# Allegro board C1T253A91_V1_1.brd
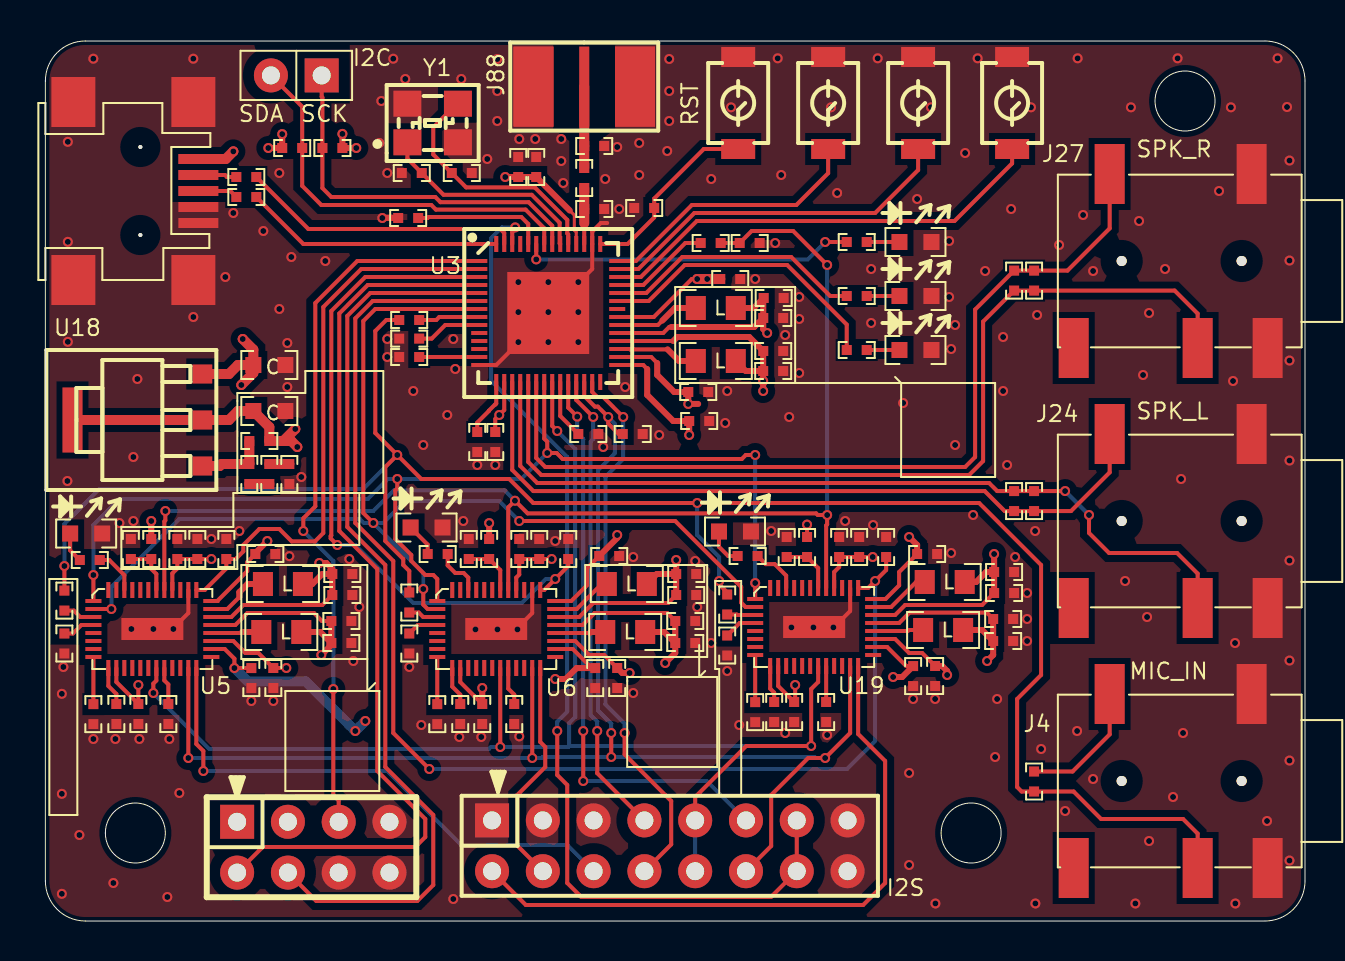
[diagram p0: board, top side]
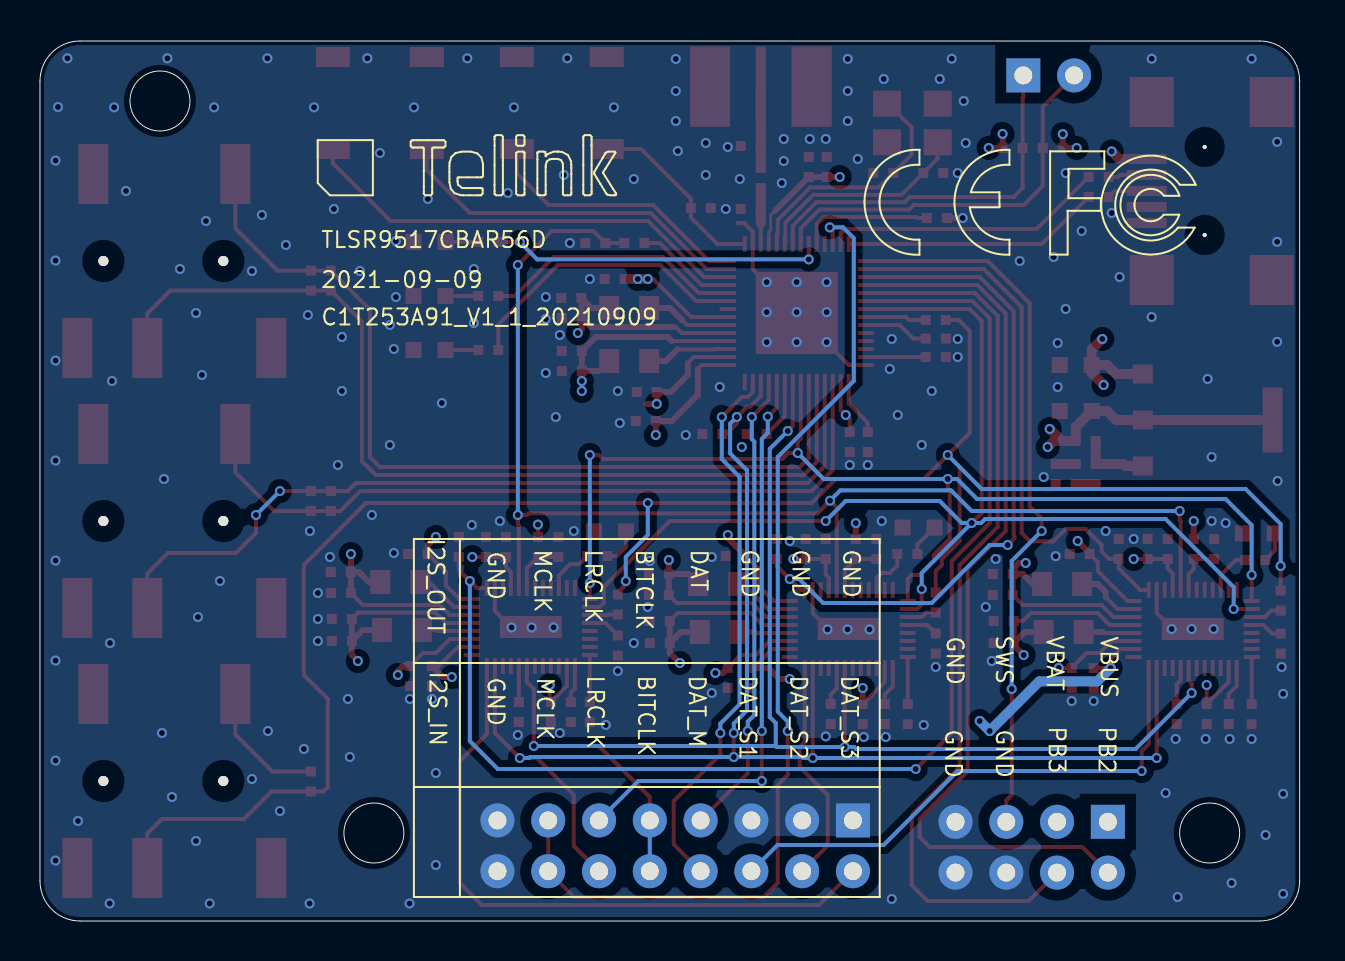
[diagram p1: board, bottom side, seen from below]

Outline 63 x 44 mm; copper layers: TOP, GND, POWER, BOTTOM. Coordinates in mm from the lower left corner of the outline.
Outline path: circle c4.5,4.4 r1.5 ; circle c46.3,4.4 r1.5 ; circle c57,41 r1.5 ; 0,42 0,2 arc(0.59,0.59) 2,0 61,0 arc(62.41,0.59) 63,2 63,42 arc(62.41,43.41) 61,44 2,44 arc(0.59,43.41) 0,42

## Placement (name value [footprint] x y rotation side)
C5  1.8pF  [0402]  27.45 35.6 180 top
C6  1pF  [0402]  27.45 38.75 180 top
C9  0.1uF  [0402]  23.65 37.7 90 top
C10  2.2uF  [0402]  24.55 37.7 90 top
C11  1uF  [0402]  29.95 35.65 180 top
C12  NC  [0402]  20.82 37.4 180 top
C13  NC  [0402]  18.32 37.4 0 top
C14  1uF  [0402]  34.25 32.1 0 top
C15  1uF  [0402]  36.42 31.15 0 top
C16  1uF  [0402]  36.4 30.15 0 top
C18  1uF  [0402]  18.2 28.2 180 top
C19  1uF  [0402]  32.65 26.45 0 top
C20  1uF  [0402]  36.4 28.5 0 top
C21  1uF  [0402]  32.7 25 0 top
C22  1uF  [0402]  36.4 27.5 0 top
C23  1uF  [0402]  21.6 23.95 270 top
C24  1uF  [0402]  22.5 23.95 270 top
C25  33pF  [0402]  29.38 24.35 0 top
C26  1uF  [0402]  27.15 24.35 0 top
C29  0.1uF  [0402]  7.6 18.6 90 top
C30  2.2uF  [0402]  6.6 18.6 90 top
C31  1uF  [0402]  9.05 18.6 90 top
C32  1uF  [0402]  11 18.35 0 top
C33  1uF  [0402]  14.85 17.35 0 top
C34  1uF  [0402]  14.85 16.3 0 top
C36  1uF  [0402]  11.4 12.15 270 top
C37  1uF  [0402]  14.8 15 0 top
C38  1uF  [0402]  2.4 10.34 270 top
C39  1uF  [0402]  10.3 12.15 270 top
C40  1uF  [0402]  14.8 13.9 0 top
C41  1uF  [0402]  3.55 10.35 270 top
C42  1uF  [0402]  4.65 10.35 270 top
C43  1uF  [0402]  6.15 10.35 270 top
C44  0.1uF  [0402]  24.7 18.6 90 top
C45  2.2uF  [0402]  23.7 18.6 90 top
C46  1uF  [0402]  26.15 18.6 90 top
C47  1uF  [0402]  28.6 12.15 270 top
C48  1uF  [0402]  21.85 10.35 270 top
C49  1uF  [0402]  32.05 16.3 0 top
C51  1uF  [0402]  28.2 18.25 0 top
C52  1uF  [0402]  32 13.9 0 top
C53  1uF  [0402]  19.6 10.34 270 top
C54  1uF  [0402]  27.5 12.15 270 top
C55  1uF  [0402]  32 15 0 top
C56  1uF  [0402]  20.75 10.35 270 top
C57  1uF  [0402]  32.05 17.35 0 top
C58  1uF  [0402]  23.45 10.35 270 top
C59  1uF  [0402]  18.2 30.05 0 top
C60  1uF  [0402]  18.2 29.12 0 top
C121  10uF  [0603C]  11.2 27.8 0 top
C122  10uF  [0603C]  11.2 25.5 0 top
C123  1uF  [0402]  35.5 10.44 270 top
C124  1uF  [0402]  37.45 10.45 270 top
C125  1uF  [0402]  36.45 10.45 270 top
C126  1uF  [0402]  39.05 10.45 270 top
C127  1uF  [0402]  47.9 15.1 0 top
C128  1uF  [0402]  44.1 18.35 0 top
C129  1uF  [0402]  47.95 17.45 0 top
C130  1uF  [0402]  43.4 12.25 270 top
C131  1uF  [0402]  44.5 12.25 270 top
C132  1uF  [0402]  47.95 16.4 0 top
C133  1uF  [0402]  47.9 14 0 top
C134  1uF  [0402]  42.05 18.7 90 top
C135  0.1uF  [0402]  40.7 18.7 90 top
C136  2.2uF  [0402]  39.7 18.7 90 top
C138  NC  [0402]  48.45 21 90 top
C140  1uF  [0402]  0.95 16.02 270 top
C141  1uF  [0402]  0.95 13.88 90 top
C142  1uF  [0402]  18.2 13.88 90 top
C143  1uF  [0402]  18.2 15.93 270 top
C144  1uF  [0402]  34.1 13.78 90 top
C145  1uF  [0402]  34.1 15.82 270 top
C146  NC  [0402]  48.45 32.02 270 top
D1  Blue  [0603-LED]  43.52 31.25 0 top
D2  Red  [0603-LED]  43.52 28.55 0 top
D4  Green  [0603-LED]  2.04 19.38 0 top
D5  Green  [0603-LED]  19.06 19.68 0 top
D6  Green  [0603-LED]  34.49 19.48 0 top
D7  Green  [0603-LED]  43.52 33.95 0 top
J3  I2C  [HDR254F-1X2X850]  11.28 42.28 0 top
J4  AIL1  [PJ-327]  62.83 7 270 top
J16  AUDIO_IN  [HDR254F-2X8X850]  40.12 5.03 180 top
J24  AOPHR  [PJ-327]  62.83 20 270 top
J27  AOPHR  [PJ-327]  62.83 33 270 top
J30  USB_MiniABF  [USB-MINI-F5]  7.65 36.5 270 top
J88  RFIN  [SMA-H]  26.95 41.72 90 top
J97  DEBUG  [HDR254F-2X4X850]  19.75 4.96 180 top
L3  2.4nH  [0402]  26.95 37.15 90 top
L4  10uH  [0805L]  33.53 30.65 0 top
L5  10uH  [0805L]  33.53 28 0 top
L6  10uH  [0805L]  11.88 16.85 0 top
L7  10uH  [0805L]  11.8 14.45 0 top
L8  10uH  [0805L]  29.08 16.85 0 top
L9  10uH  [0805L]  29 14.45 0 top
L10  10uH  [0805L]  44.9 14.55 0 top
L11  10uH  [0805L]  44.98 16.95 0 top
R1  4.7K  [0402]  18.14 35.15 0 top
R2  1K  [0402]  40.58 31.25 0 top
R3  1K  [0402]  40.58 28.55 0 top
R6  NC  [0402]  49.45 21 90 top
R13  2.2K  [0402]  12.35 38.65 0 top
R14  2.2K  [0402]  14.36 38.65 180 top
R23  510R  [0402]  33.27 33.9 0 top
R26  240R  [0402]  35.23 33.9 180 top
R32  2.2K  [0402]  5.29 18.6 90 top
R33  330R  [0402]  4.28 18.6 90 top
R41  2.2K  [0402]  22.2 18.6 90 top
R42  330R  [0402]  21.18 18.6 90 top
R45  33  [0402]  10.05 37.2 0 top
R65  33  [0402]  10.05 36.2 0 top
R68  1K  [0402]  10.7 24 0 top
R69  430R  [0402]  10.2 22.35 270 top
R101  1.15K  [0402]  11.2 22.35 90 top
R102  780R  [0402]  12.2 22.35 270 top
R104  2.2K  [0402]  38.09 18.7 90 top
R105  330R  [0402]  37.08 18.7 90 top
R109  1K  [0402]  2.22 18.05 180 top
R110  1K  [0402]  19.62 18.35 180 top
R111  1K  [0402]  35.12 18.25 180 top
R112  0R  [0402]  49.45 6.97 90 top
R119  1K  [0402]  40.58 33.95 0 top
R120  NC  [0402]  49.45 32.02 270 top
SW1  BUTTON  [BUTSMD2PX4_00Y3_00_NH]  34.65 40.9 180 top
SW2  BUTTON  [BUTSMD2PX4_00Y3_00_NH]  39.15 40.9 180 top
SW3  BUTTON  [BUTSMD2PX4_00Y3_00_NH]  43.65 40.9 180 top
SW4  BUTTON  [BUTSMD2PX4_00Y3_00_NH]  48.35 40.9 180 top
U3  TLSR9517C  [QFN_7X7_56PIN_0P4_4P10X4P10]  25.15 30.4 0 top
U5  TLSC9805A  [QFN_4X6_40PIN_0P4_1P10X3P10]  5.35 14.6 0 top
U6  TLSC9805A  [QFN_4X6_40PIN_0P4_1P10X3P10]  22.55 14.6 0 top
U18  LM1117-ADJ  [SOT-223]  4.35 25.05 90 top
U19  TLSC9805A  [QFN_4X6_40PIN_0P4_1P10X3P10]  38.45 14.7 0 top
Y1  24MHz-12pF-+/-20ppm  [OSCCC250X320X110]  19.37 39.9 90 top

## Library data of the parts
C5 C6 = C1608_NC
C9-C11 C14-C16 C18-C26 C29-C34 C36-C49 C51-C60 C123-C136 C140-C145 = C1005X5R1C104K
C12 C13 = C1005_NC
C121 = C1608X5R0J106M
C122 = C1608X5R1C105M
C138 C146 = C1005X5R1C105K
D1 D2 D4-D7 = 0603D_Red
J3 = HEADER 2: User Part Number: pn; Tolerance: RichardLC
J4 J24 J27 = PJ327_2
J16 = HEADER 8X2: User Part Number: pn; Tolerance: RichardLC
J30 = USB_MiniABF_5pin: User Part Number: pn; Tolerance: RichardLC
J88 = SMA_JACK_2
J97 = HEADER 4X2: User Part Number: pn; Tolerance: RichardLC
L3 = MLK1608_000R
L4-L11 = IND
R1 R6 R13 R14 R23 R26 R32 R33 R41 R42 R104 R105 R112 R120 = RS0402K104JT
R2 R3 R109-R111 R119 = RS0402K332JT
R45 R65 = RS0603K330JT
R68 R69 R101 R102 = RS0603K104JT
SW1-SW4 = SW2PIN_3x4
U3 = TLSR9517C_1: Tolerance: RichardLC
U5 U6 U19 = TLSC9805A_0
U18 = XC62FP3302_0.3V_SOT-89
Y1 = CRYSTAL4/SM_0: Tolerance: RichardLC

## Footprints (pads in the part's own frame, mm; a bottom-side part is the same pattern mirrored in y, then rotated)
0402
  rect 0.5x0.5 smd: 1(-0.5,0) 2(0.5,0)
0603-LED
  rect 0.8x0.8 smd: A(-0.8,0) C(0.8,0)
0603C
  rect 0.8x0.8 smd: 1(-0.8,0) 2(0.8,0)
0805L
  rect 1x1.2 smd: 1(-1,0) 2(1,0)
BUTSMD2PX4_00Y3_00_NH
  rect 1.7x1 smd: 1(0,2.3) 2(0,-2.3)
HDR254F-1X2X850
  rect 1.7x1.7 hole 0.9: 1(2.54,0)
  round 1.7 hole 0.9: 2(0,0)
HDR254F-2X4X850
  rect 1.7x1.7 hole 0.9: 1(10.16,0)
  round 1.7 hole 0.9: 2(10.16,2.54) 3(7.62,0) 4(7.62,2.54) 5(5.08,0) 6(5.08,2.54) 7(2.54,0) 8(2.54,2.54)
HDR254F-2X8X850
  rect 1.7x1.7 hole 0.9: 1(17.78,0)
  round 1.7 hole 0.9: 2(17.78,2.54) 3(15.24,0) 4(15.24,2.54) 5(12.7,0) 6(12.7,2.54) 7(10.16,0) 8(10.16,2.54) 9(7.62,0) 10(7.62,2.54) 11(5.08,0) 12(5.08,2.54) 13(2.54,0) 14(2.54,2.54) 15(0,0) 16(0,2.54)
OSCCC250X320X110
  rect 1.3x1.4 smd: 1(-0.965,1.265) 2(-0.965,-1.265) 3(0.965,-1.265) 4(0.965,1.265)
PJ-327
  round 0.5 hole 1: (0,-3) (0,-9)
  rect 3x1.5 smd: 1(-4.35,-2.5) 2(4.35,-5.2) 3(-4.35,-9.6) 4(4.35,-11.4) 5(4.35,-1.7)
QFN_4X6_40PIN_0P4_1P10X3P10
  rect 0.8x0.2 smd: 1(-2.95,1.4) 2(-2.95,1) 3(-2.95,0.6) 4(-2.95,0.2) 5(-2.95,-0.2) 6(-2.95,-0.6) 7(-2.95,-1) 8(-2.95,-1.4) 21(2.95,-1.4) 22(2.95,-1) 23(2.95,-0.6) 24(2.95,-0.2) 25(2.95,0.2) 26(2.95,0.6) 27(2.95,1) 28(2.95,1.4)
  rect 0.2x0.8 smd: 9(-2.2,-1.95) 10(-1.8,-1.95) 11(-1.4,-1.95) 12(-1,-1.95) 13(-0.6,-1.95) 14(-0.2,-1.95) 15(0.2,-1.95) 16(0.6,-1.95) 17(1,-1.95) 18(1.4,-1.95) 19(1.8,-1.95) 20(2.2,-1.95) 29(2.2,1.95) 30(1.8,1.95) 31(1.4,1.95) 32(1,1.95) 33(0.6,1.95) 34(0.2,1.95) 35(-0.2,1.95) 36(-0.6,1.95) 37(-1,1.95) 38(-1.4,1.95) 39(-1.8,1.95) 40(-2.2,1.95)
  rect 3.1x1.1 smd: 41(0,0)
QFN_7X7_56PIN_0P4_4P10X4P10
  rect 0.8x0.2 smd: 1(-3.45,2.6) 2(-3.45,2.2) 3(-3.45,1.8) 4(-3.45,1.4) 5(-3.45,1) 6(-3.45,0.6) 7(-3.45,0.2) 8(-3.45,-0.2) 9(-3.45,-0.6) 10(-3.45,-1) 11(-3.45,-1.4) 12(-3.45,-1.8) 13(-3.45,-2.2) 14(-3.45,-2.6) 29(3.45,-2.6) 30(3.45,-2.2) 31(3.45,-1.8) 32(3.45,-1.4) 33(3.45,-1) 34(3.45,-0.6) 35(3.45,-0.2) 36(3.45,0.2) 37(3.45,0.6) 38(3.45,1) 39(3.45,1.4) 40(3.45,1.8) 41(3.45,2.2) 42(3.45,2.6)
  rect 0.2x0.8 smd: 15(-2.6,-3.45) 16(-2.2,-3.45) 17(-1.8,-3.45) 18(-1.4,-3.45) 19(-1,-3.45) 20(-0.6,-3.45) 21(-0.2,-3.45) 22(0.2,-3.45) 23(0.6,-3.45) 24(1,-3.45) 25(1.4,-3.45) 26(1.8,-3.45) 27(2.2,-3.45) 28(2.6,-3.45) 43(2.6,3.45) 44(2.2,3.45) 45(1.8,3.45) 46(1.4,3.45) 47(1,3.45) 48(0.6,3.45) 49(0.2,3.45) 50(-0.2,3.45) 51(-0.6,3.45) 52(-1,3.45) 53(-1.4,3.45) 54(-1.8,3.45) 55(-2.2,3.45) 56(-2.6,3.45)
  rect 4.1x4.1 smd: 57(0,0)
SMA-H
  rect 4x0.5 smd: 1(0,0)
  rect 4x2 smd: 2(0,-2.54) 3(0,2.54) 4(0,-2.54) 5(0,2.54)
SOT-223
  rect 0.95x1 smd: 1(-2.3,-3.495) 2(0,-3.495) 3(2.3,-3.495)
  rect 3.25x1 smd: 4(0,2.995)
USB-MINI-F5
  round 0.2 hole 0.9 unplated: (-2.2,-2.9) (2.2,-2.9)
  rect 0.5x2 smd: 1(-1.6,0) 2(-0.8,0) 3(0,0) 4(0.8,0) 5(1.6,0)
  rect 2.5x2.2 smd: 6(-4.45,-6.25) 7(4.45,-6.25) 8(-4.45,-0.25) 9(4.45,-0.25)

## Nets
GND: C5.1 C6.1 C9.2 C10.2 C11.2 C12.1 C13.1 C14.2 C15.2 C16.2 C18.2 C19.2 C20.2 C21.2 C22.2 C23.2 C24.2 C25.2 C26.2 C29.2 C30.2 C31.2 C32.2 C33.2 C34.2 C36.2 C37.2 C38.2 C39.2 C40.2 C41.2 C42.2 C43.2 C44.2 C45.2 C46.2 C47.2 C48.2 C49.2 C51.2 C52.2 C53.2 C54.2 C55.2 C56.2 C57.2 C58.2 C60.1 C121.2 C122.2 C123.2 C124.2 C125.2 C126.2 C127.2 C128.2 C129.2 C130.2 C131.2 C132.2 C133.2 C134.2 C135.2 C136.2 C141.1 C142.1 C144.1 D1.C(CATHODE) D2.C(CATHODE) D4.C(CATHODE) D5.C(CATHODE) D6.C(CATHODE) D7.C(CATHODE) J4.1 J4.5 J16.1 J16.3 J16.5 J16.15 J16.16 J24.1 J24.5 J27.1 J27.5 J30.4(ID) J30.5(GND) J30.6(S1) J30.7(S2) J30.8(S3) J30.9(S4) J88.2 J88.3 J88.4 J88.5 J97.6 J97.7 J97.8 R1.1 R26.1 R33.2 R42.2 R102.2 R105.2 SW1.2 SW2.2 SW3.2 SW4.2 U3.14(VSSA) U3.44(GANT) U3.57(GND) U5.30(GANT) U5.41(GND) U6.30(GANT) U6.41(GND) U19.30(GANT) U19.41(GND) Y1.2 Y1.4
VBUS: C121.1 J30.1(V_BUS) J97.1 U18.3(VIN)
BITCLK: J16.9 J16.10 U3.22(PC[3]) U5.15(PC[3]) U6.15(PC[3]) U19.15(PC[3])
CLK_S1: R23.2 R26.2 U5.33(XC1) U6.33(XC1) U19.33(XC1)
DAC_DAT_M: J16.8 U3.27(PC[7])
DAC_DAT_S1: J16.6 U5.20(PC[7])
DAC_DAT_S2: J16.4 U6.20(PC[7])
DAC_DAT_S3: J16.2 U19.20(PC[7])
DAC_LR: C25.1 J16.12 U3.26(PC[6]) U5.19(PC[6]) U6.19(PC[6]) U19.19(PC[6])
RST_S1: C31.1 U3.2(PB[0]) U5.29(RESETB)
RST_S2: C46.1 U3.3(PB[1]) U6.29(RESETB)
RST_S3: C134.1 U3.6(PB[4]) U19.29(RESETB)
SWS_S1: U3.21(PC[0]) U5.1(PA[7]) U6.1(PA[7]) U19.1(PA[7])
SYNC: U3.7(PB[6]) U5.2(PB[6]) U6.2(PB[6]) U19.2(PB[6])
TL_ANT: C5.2 L3.1 U3.45(ANT)
TL_AONHPL: C138.2 J24.2 R6.2 U3.18(AONHPL)
TL_AONHPR: C146.2 J27.2 R120.2 U3.19(AONHPR)
TL_AOPHPL: C138.1 J24.3 R6.1 U3.17(AOPHPL)
TL_AOPHPR: C146.1 J27.3 R120.1 U3.20(AOPHPR)
TL_AUDIO_S1: C59.1 C140.1 C143.1 C145.1 J4.2 R112.1
TL_AVD_M: C15.1 C16.1 C24.1 L4.2 U3.16(AVD) U3.33(FVDD1V8)
TL_AVD_S1: C33.1 C34.1 C42.1 L6.2 U5.10(AVD) U5.26(FVDD1V8)
TL_AVD_S2: C48.1 C49.1 C57.1 L8.2 U6.10(AVD) U6.26(FVDD1V8)
TL_AVD_S3: C124.1 C129.1 C132.1 L11.2 U19.10(AVD) U19.26(FVDD1V8)
TL_AVDD3_M: C14.1 C19.1 R13.1 R14.1 U3.30(VDD3) U3.35(AVDD3)
TL_AVDD3_S1: C32.1 C36.1 R32.2 U5.23(VDD3) U5.28(AVDD3)
TL_AVDD3_S2: C47.1 C51.1 R41.2 U6.23(VDD3) U6.28(AVDD3)
TL_AVDD3_S3: C128.1 C131.1 R104.2 U19.23(VDD3) U19.28(AVDD3)
TL_PA0_MCLK_OUT: J16.13 J16.14 U3.54(PA[0])
TL_PA5_DM_M: R45.2 U3.55(PA[5])
TL_PA6_DP_M: R65.2 U3.56(PA[6])
TL_PA7_SWS_M: J97.5 U3.1(PA[7])
TL_PB2_UTX: J97.2 U3.4(PB[2])
TL_PB3_URX: J97.4 U3.5(PB[3])
TL_PC4_ADC_LR: J16.11 U3.24(PC[4])
TL_PC5_ADC_DAT: J16.7 U3.25(PC[5])
TL_PD1_LED2_M: R3.1 U3.37(PD[1])
TL_PD2_LED1_M: R2.1 U3.38(PD[2])
TL_PD3_24M_CLK_OUT: R23.1 U3.39(PD[3])
TL_PD4_BUTTON1_M: SW4.1 U3.40(PD[4])
TL_PD5_BUTTON2_M: SW3.1 U3.41(PD[5])
TL_PD6_BUTTON3_M: SW2.1 U3.42(PD[6])
TL_PE0_I2C_SCK_M: J3.1 R14.2 U3.49(PE[0])
TL_PE2_I2C_SDA_M: J3.2 R13.2 U3.50(PE[2])
TL_PE3_LED1_M: R119.1 U3.51(PE[3])
TL_PE3_LED_S1: R109.1 U5.38(PE[3])
TL_PE3_LED_S2: R110.1 U6.38(PE[3])
TL_PE3_LED_S3: R111.1 U19.38(PE[3])
TL_RFVDD1V4_M: C9.1 C10.1 C20.1 C22.1 L5.2 U3.32(VDD1V4) U3.46(VLINE_PAD)
TL_RFVDD1V4_S1: C29.1 C30.1 C37.1 C40.1 L7.2 U5.25(VDD1V4) U5.32(VLINE_PAD)
TL_RFVDD1V4_S2: C44.1 C45.1 C52.1 C55.1 L9.2 U6.25(VDD1V4) U6.32(VLINE_PAD)
TL_RFVDD1V4_S3: C127.1 C133.1 C135.1 C136.1 L10.2 U19.25(VDD1V4) U19.32(VLINE_PAD)
TL_RST_M: C11.1 SW1.1 U3.43(RESETB)
TL_VBAT: C21.1 C39.1 C54.1 C122.1 C130.1 J97.3 R68.2 U3.29(VBAT) U5.22(VBAT) U6.22(VBAT) U18.2(VOUT#2) U18.4(VOUT#4) U19.22(VBAT)
TL_XC1_M: C12.2 U3.47(XC1) Y1.3
TL_XC2_M: C13.2 U3.48(XC2) Y1.1
TL_XC2_S1: R32.1 R33.1 U5.34(XC2)
TL_XC2_S2: R41.1 R42.1 U6.34(XC2)
TL_XC2_S3: R104.1 R105.1 U19.34(XC2)
N20339251: C18.1 U3.13(VCAP)
N20339567: C23.1 U3.15(VREFP_CODEC)
N20339740: C26.1 U3.23(VDDDEC)
N20340124: L4.1 U3.34(VDD1V8_O)
N20340134: L5.1 U3.31(VDD1V4_O)
N20349172: C38.1 U5.8(VCAP)
N20349354: C41.1 U5.9(VREFP_CODEC)
N20350037: C43.1 U5.16(VDDDEC)
N20350580: L7.1 U5.24(VDD1V4_O)
N20350582: L6.1 U5.27(VDD1V8_O)
N20367658: C53.1 U6.8(VCAP)
N20367674: C56.1 U6.9(VREFP_CODEC)
N20367749: C58.1 U6.16(VDDDEC)
N20367829: L9.1 U6.24(VDD1V4_O)
N20367831: L8.1 U6.27(VDD1V8_O)
N20435584: C6.2 J88.1 L3.2
N20442183: C59.2 U3.8(AIPL1)
N20442186: C60.2 U3.9(AINL1)
N20446937: J30.3(D+) R65.1
N20446945: J30.2(D-) R45.1
N20447032: R69.2 R101.1
N20447038: R68.1 R69.1 U18.1(ADJ)
N20447058: R101.2 R102.1
N20449953: C123.1 U19.8(VCAP)
N20449969: C125.1 U19.9(VREFP_CODEC)
N20450013: C126.1 U19.16(VDDDEC)
N20450064: L11.1 U19.27(VDD1V8_O)
N20450066: L10.1 U19.24(VDD1V4_O)
N20490300: D4.A(ANODE) R109.2
N20490451: D5.A(ANODE) R110.2
N20490658: D6.A(ANODE) R111.2
N20496511: R1.2 U3.52(PE[6])
N20499472: C141.2 U5.4(AINL1)
N20499474: C140.2 U5.3(AIPL1)
N20499818: C142.2 U6.4(AINL1)
N20499820: C143.2 U6.3(AIPL1)
N20500173: C144.2 U19.4(AINL1)
N20500175: C145.2 U19.3(AIPL1)
N20500676: J4.3 R112.2
N202186321: D1.A(ANODE) R2.2
N202186660: D2.A(ANODE) R3.2
N205071311: D7.A(ANODE) R119.2

Pads without a net: J4 4; J24 4; J27 4; U3 10 11 12 28 36 53; U5 5 6 7 11 12 13 14 17 18 21 31 35 36 37 39 40; U6 5 6 7 11 12 13 14 17 18 21 31 35 36 37 39 40; U19 5 6 7 11 12 13 14 17 18 21 31 35 36 37 39 40

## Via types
v1: diameter 0.5, hole 0.3, TOP to BOTTOM, 294 vias

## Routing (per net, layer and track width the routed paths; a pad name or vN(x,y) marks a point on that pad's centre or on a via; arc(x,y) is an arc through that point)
GND: length 21.1
  TOP w0.2: U6.30 24.35,15.4 23.55,14.6 U6.41 ; U5.30 7.15,15.4 6.35,14.6 v1(5.4,14.6) U5.41 ; U19.41 39.45,14.7 40.25,15.5 U19.30 ; U3.14 22.55,27.8 U3.57 27.35,32.6 U3.44 27.35,34.47 27.78,34.9 28.1,34.9
  TOP w0.3: R1.1 v1(16.85,35.15)
  vias: v1(0.82,11.36) v1(0.82,6.36) v1(0.82,1.36) v1(0.9,12.7) v1(1.12,38.96) v1(1.12,33.96) v1(1.12,28.96) v1(1.1,22) v1(1.7,4.3) v1(2.4,43.11) v1(2.4,9.1) v1(3.4,1.9) v1(3.5,9.1) v1(3.7,19.9) v1(4.3,14.6) v1(4.4,23.2) v1(4.4,20) v1(4.6,27.1) v1(4.7,9.1) v1(6.1,1.2) v1(6.2,9.1) v1(6.4,14.6) v1(6.7,6.4) v1(7.4,43.11) v1(7.4,30.2) v1(8.3,19.1) v1(9,32.2) v1(9.4,35.4) v1(9.7,19.5) v1(10.3,11) v1(10.9,34.5) v1(11.4,11) v1(11.7,37.4) v1(11.7,30.6) v1(12.1,28.9) v1(12.1,26.7) v1(12.2,18.24) v1(12.3,33.2) v1(12.8,22.2) v1(14,33) v1(15.2,18.1) v1(15.4,13) v1(15.7,15.7) v1(16.7,38.9) v1(16.8,41) v1(17.1,37.4) v1(17.1,29.1) v1(17.1,28.2) v1(17.4,43.11) v1(18,42.1) v1(18.2,12.7) v1(18.4,26.5) v1(18.8,9.8) v1(18.9,23.8) v1(20.1,25.3) v1(20.4,29.1) v1(20.4,1.1) v1(20.5,27.6) v1(20.7,9.2) v1(20.8,42.1) v1(20.9,20) v1(21.51,14.58) v1(21.6,22.8) v1(21.8,9.2) v1(22.1,38.1) v1(22.5,22.8) v1(22.6,43.1) v1(22.6,41.5) v1(22.6,40) v1(22.61,14.58) v1(23.61,14.58) v1(23.7,39.1) v1(23.65,31.95) v1(23.65,30.45) v1(23.65,28.95) v1(23.7,9.23) v1(24.5,39.1) v1(25.15,31.95) v1(25.15,30.45) v1(25.15,28.95) v1(25.5,19) v1(25.8,39.1) v1(25.8,38) v1(25.9,36.9) v1(26.65,31.95) v1(26.65,30.45) v1(26.65,28.95) v1(27.9,23.7) v1(28,37.1) v1(28.6,38.7) v1(28.7,35.6) v1(29,26.7) v1(29.4,18.2) v1(29.4,11.4) v1(29.7,38.9) v1(29.7,37.3) v1(30.7,24.3) v1(31.1,38.5) v1(31.2,43.1) v1(31.2,41.5) v1(31.2,40) v1(32.5,18) v1(32.6,15.7) v1(33.3,37.1) v1(33.3,13.9) v1(34,24.9) v1(34.1,26.5) v1(34.1,12.5) v1(34.29,40.68) v1(34.7,9.8) v1(35.5,32.1) v1(36.3,19.5) v1(36.5,33.9) v1(36.63,43.14) v1(36.8,37.3) v1(37,29.3) v1(37,9.4) v1(37.2,25.2) v1(37.31,14.68) v1(37.7,31.2) v1(37.7,30.1) v1(37.7,27.4) v1(38.41,14.68) v1(39.1,9.3) v1(39.29,40.68) v1(39.41,14.68) v1(39.6,36.4) v1(40,20) v1(41.3,32.6) v1(41.3,29.9) v1(41.4,19.8) v1(41.63,43.14) v1(42.9,25.9) v1(43.2,7.4) v1(43.2,2.8) v1(43.4,11.1) v1(43.6,36.1) v1(44.29,40.68) v1(44.5,11.1) v1(44.51,0.88) v1(45.2,34) v1(45.2,31.2) v1(45.3,28.6) v1(45.3,18.4) v1(45.5,29.8) v1(45.5,23.8) v1(46,38.4) v1(46.4,20.3) v1(46.63,43.14) v1(47,32.5) v1(47.5,8.2) v1(47.6,11.1) v1(47.9,29.2) v1(47.9,26.5) v1(48.1,22.8) v1(48.3,35.6) v1(48.5,18.2) v1(49.1,16.4) v1(49.1,15.1) v1(49.1,14) v1(49.29,40.68) v1(49.5,19.5) v1(49.51,0.88) v1(49.6,30.3) v1(49.8,8.6) v1(50.7,33.8) v1(51,5.5) v1(51.63,43.14) v1(51.6,9.5) v1(51.9,35.3) v1(52.4,32.5) v1(52.4,7.1) v1(54,17) v1(54.29,40.68) v1(54.51,0.88) v1(54.7,35) v1(54.9,27.3) v1(55.1,15.2) v1(55.2,30.4) v1(55.2,4) v1(56,32.6) v1(56.4,6.2) v1(56.63,43.14) v1(56.8,22.1) v1(56.9,9.4) v1(58.7,36.5) v1(59.29,40.68) v1(59.4,27) v1(59.5,13.9) v1(59.51,0.88) v1(61.1,5) v1(61.63,43.14) v1(62.1,40.7) v1(62.22,38.02) v1(62.22,33.02) v1(62.22,28.02) v1(62.22,23.02) v1(62.22,18.02) v1(62.22,13.02) v1(62.22,8.02) v1(62.22,3.02)
VBUS: length 7.4
  TOP w0.5: v1(9.87,29.1) 10.4,28.57 C121.1 ; v1(9.4,38.48) 9.02,38.1 J30.1 ; C121.1 10.4,27.4 v1(9.8,26.8) ; C121.1 9.63,27.8 9.18,27.35 U18.3
BITCLK: length 72.9
  TOP w0.2: U19.15 38.65,11.95 38.3,11.6 v1(38.3,8.75) 35.05,8.75 32.5,6.2 J16.9 ; U6.15 v1(22.75,8.7) ; v1(5.4,11.4) 5.4,11.87 5.55,12.02 U5.15 ; U3.22 25.35,24.75 v1(25.6,24.5)
  BOTTOM w0.2: 26.2,8.75 26.2,9.9 26.5,10.2 26.5,23.6 v1(25.6,24.5) ; 26.2,8.75 v1(38.3,8.75) ; 26.2,8.75 26.15,8.7 v1(22.75,8.7) 22.28,8.7 22.18,8.6 8.2,8.6 v1(5.4,11.4) ; J16.10 J16.9
CLK_S1: length 65.1
  TOP w0.2: U6.33 23.15,20.68 v1(23.48,21.02) 24.12,20.38 38.55,20.38 38.63,20.3 v1(39.1,20.3) 39.1,19.83 39.05,19.78 U19.33 ; U5.33 5.95,19.98 6,20.03 v1(6,20.5) ; R23.2 R26.2 35.33,34.5 37.4,34.5 v1(39.1,32.8)
  BOTTOM w0.2: v1(6,20.5) 16.4,20.5 17.43,21.53 22.97,21.53 v1(23.48,21.02) ; v1(39.1,32.8) v1(39.1,20.3)
DAC_DAT_M: length 27.6
  TOP w0.2: v1(28.97,9.4) 28.97,8.33 31.3,6 31.3,3.83 J16.8 ; v1(28.9,25.2) 27.9,26.2 27.6,26.2 27.35,26.45 U3.27
  BOTTOM w0.2: v1(28.9,25.2) 28.9,23.1 28.01,22.21 28.01,10.83 28.97,9.87 v1(28.97,9.4)
DAC_DAT_S1: length 26.9
  TOP w0.2: v1(7.9,7.5) 7.9,8.5 7.55,8.85 U5.20
  BOTTOM w0.2: J16.6 26.11,3.8 20.8,3.8 17.1,7.5 v1(7.9,7.5)
DAC_DAT_S2: length 11.4
  TOP w0.2: J16.4 23.6,3.77 23.6,6.3 25,7.7 25,8.7 24.75,8.95 U6.20
DAC_DAT_S3: length 32.2
  TOP w0.2: U19.20 40.65,9.35 42,8 42,1.9 40.9,0.8 24.03,0.8 J16.2
DAC_LR: length 75.2
  TOP w0.2: J16.12 36.3,3.75 36.3,6.3 38.15,8.15 v1(39,8.15) 40.25,9.4 U19.19 ; U6.19 v1(24.35,8.15) ; U5.19 v1(7.15,8.15) ; U3.26 26.95,26.25 27.48,25.72 27.63,25.72 v1(28.15,25.2) 28.15,24.88 28.68,24.35 C25.1 ; v1(28.3,9.4) v1(28.3,8.2)
  BOTTOM w0.2: v1(7.15,8.15) v1(24.35,8.15) 24.82,8.15 24.87,8.2 v1(28.3,8.2) 38.48,8.2 38.53,8.15 v1(39,8.15) ; v1(28.15,25.2) 28.48,24.87 28.48,23.38 27.64,22.54 27.64,10.53 28.3,9.87 v1(28.3,9.4)
RST_S1: length 28.4
  TOP w0.2: U5.29 7.97,16.55 9.05,17.63 C31.1 9.52,18.1 9.9,18.48 9.9,18.8 10.7,19.6 11.7,19.6 12.32,18.98 13.48,18.98 13.9,19.4 13.9,30.7 15.8,32.6 U3.2
RST_S2: length 34.8
  TOP w0.2: U3.3 16,32.2 14.3,30.5 14.3,19.28 14.27,19.24 14.27,19.13 v1(14.6,18.8) ; C46.1 26.15,17.75 v1(25.5,17.1) 24.95,16.55 U6.29
  BOTTOM w0.2: v1(14.6,18.8) 15.5,18.8 18.4,15.9 23.83,15.9 25.03,17.1 v1(25.5,17.1)
RST_S3: length 63.9
  TOP w0.2: U3.6 16.37,31 15.5,30.13 15.5,19.9 17.4,18 17.4,9.4 v1(19.2,7.6) ; U19.29 41.15,16.65 v1(41.5,17) 42.05,17.55 C134.1
  BOTTOM w0.2: v1(19.2,7.6) 40.1,7.6 41.5,9 v1(41.5,17)
SWS_S1: length 56.7
  TOP w0.2: v1(35.5,23.3) 35.03,23.3 34.83,23.1 25.87,23.1 25.57,23.4 v1(25.1,23.4) 25.1,23.97 24.95,24.12 U3.21 ; v1(17.6,22.1) 17.6,21.63 17.5,21.53 17.5,19.1 18.3,18.3 18.3,18 19,17.3 19.4,17.3 19.6,17.1 U6.1 ; v1(2.4,17.3) U5.1 ; U19.1 v1(35.5,16.9)
  BOTTOM w0.2: v1(2.4,17.3) 2.4,19.8 3.7,21.1 16.13,21.1 17.13,22.1 v1(17.6,22.1) 23.8,22.1 v1(25.1,23.4) ; v1(35.5,16.9) v1(35.5,23.3)
SYNC: length 61.1
  TOP w0.2: U6.2 19.12,15.6 18.9,15.82 v1(18.9,16.6) ; U3.7 16.5,30.6 15.9,30 15.9,20.4 v1(16.4,19.9) ; U19.2 35.02,15.7 34.8,15.92 34.8,16.7 31.5,20 v1(23.7,20) ; v1(3.3,15.6) U5.2
  BOTTOM w0.2: v1(16.4,19.9) 18.9,17.4 v1(18.9,16.6) ; v1(16.4,19.9) 15.93,19.9 15.73,20.1 6.7,20.1 3.3,16.7 v1(3.3,15.6) ; v1(16.4,19.9) 16.9,19.9 18,21 22.7,21 v1(23.7,20)
TL_ANT: length 2.8
  TOP w0.2: U3.45 26.95,34.89
  TOP w0.5: L3.1 C5.2 26.95,34.89
TL_AONHPL: length 42.6
  TOP w0.2: U3.18 23.75,22.75 24.6,21.9 47.2,21.9 47.6,21.5 C138.2 R6.2 v1(51,21.5) ; v1(52.2,20.3) 52.2,19.4 53.2,18.4 56.6,18.4 57.63,17.37 J24.2
  BOTTOM w0.2: v1(51,21.5) v1(52.2,20.3)
TL_AONHPR: length 47.8
  TOP w0.2: U3.19 24.15,22.95 24.8,22.3 46.2,22.3 46.9,23 46.9,29.97 C146.2 R120.2 56.48,31.52 57.63,30.37 J27.2
TL_AOPHPL: length 37.9
  TOP w0.2: U3.17 23.35,22.55 24.4,21.5 46.98,21.5 47.98,20.5 C138.1 R6.1 51.3,20.5 53.23,22.43 J24.3
TL_AOPHPR: length 44.6
  TOP w0.2: J27.3 53.23,34.63 51.12,32.52 R120.1 C146.1 46.5,30.57 46.5,23.2 46,22.7 25,22.7 24.55,23.15 U3.20
TL_AUDIO_S1: length 100.1
  TOP w0.2: C59.1 17.05,30.05 16.5,29.5 16.5,24.4 v1(17.6,23.3) ; v1(17.6,23.3) 18.8,22.1 23.2,22.1 24.4,20.9 v1(32.6,20.9) 46.7,20.9 49.8,17.8 49.8,12.3 48.6,11.1 48.6,6.7 48.82,6.47 R112.1 51.42,6.47 52.8,5.1 56.9,5.1 57.63,4.37 J4.2 ; v1(17.6,23.3) 17,22.7 17,19 17.9,18.1 17.9,17.8 18.2,17.5 C143.1 ; v1(33.7,17) 33.7,16.83 34.1,16.43 C145.1 ; C140.1 v1(0.95,17.75)
  BOTTOM w0.2: v1(33.7,17) 33.7,18.2 32.6,19.3 v1(32.6,20.9) ; v1(0.95,17.75) 0.95,19.85 2.7,21.6 15.9,21.6 v1(17.6,23.3)
TL_AVD_M: length 13.7
  TOP w0.2: 31.3,29.7 31.2,29.7 30.9,29.4 U3.33 ; C24.1 22.5,25.1 v1(22.7,25.3) 22.95,25.55 U3.16
  TOP w0.3: v1(36.1,29.4) 35.9,29.6 C16.1 ; C16.1 35.45,29.7 31.3,29.7 ; C16.1 35.9,31.13 ; L4.2 35.42,30.65 35.9,31.13 ; 35.9,31.13 C15.1
TL_AVD_S1: length 13.5
  TOP w0.2: U5.26 9.3,15.2 9.9,15.8 13.85,15.8 C34.1 ; v1(4.65,11.8) C42.1 3.55,11.95 U5.10
  TOP w0.3: C34.1 C33.1 ; C33.1 14.35,17.6 14.05,17.9 v1(13.7,17.9) ; C33.1 13.85,17.35 13.35,16.85 L6.2
TL_AVD_S2: length 13
  TOP w0.2: U6.10 20.75,11.94 21.44,11.26 21.44,11.26 C48.1 ; U6.26 26.7,15.2 27.4,15.9 31.15,15.9 C49.1
  TOP w0.3: C49.1 C57.1 ; C57.1 v1(31.55,18.05) ; C57.1 30.58,17.35 L8.2 ; C48.1 v1(21.85,11.65)
TL_AVD_S3: length 13.1
  TOP w0.2: U19.10 36.65,11.75 C124.1 37.5,11 v1(37.5,11.8) ; U19.26 42.5,15.3 43,15.8 46.85,15.8 C132.1
  TOP w0.3: C129.1 v1(47.45,18.35) ; C129.1 C132.1 ; C129.1 47.05,17.45 46.55,16.95 L11.2
TL_AVDD3_M: length 14.5
  TOP w0.2: U3.35 30.43,30.2 32.33,32.1 v1(32.6,32.1) ; U3.30 30.3,28.2 30.6,27.9
  TOP w0.3: v1(14.86,39.35) R14.1 v1(15.55,38.65) ; 30.6,27.9 30.6,27.3 31.45,26.45 C19.1 v1(32.15,25.85) 32.65,25.85 ; v1(11.85,39.34) R13.1 v1(11.15,38.65)
  TOP w0.5: C14.1 v1(33.1,32.1) v1(32.6,32.1)
TL_AVDD3_S1: length 9.5
  TOP w0.2: C32.1 10.09,17.94 10.09,17.49 8.6,16 U5.28 ; U5.23 9.4,14 10,13.4 10.65,13.4 C36.1 v1(12.05,12.65)
  TOP w0.3: v1(11.1,19) 10.5,18.4 C32.1 ; v1(5.29,20) R32.2
TL_AVDD3_S2: length 10.2
  TOP w0.2: C47.1 27.95,13.3 27.2,13.3 26.5,14 U6.23 ; U6.28 26.3,16 27.1,16.8 27.1,17.65 C51.1
  TOP w0.3: C47.1 28.85,12.4 v1(29.22,12.4) ; v1(28.6,19.3) 28.6,19.15 C51.1 ; R41.2 v1(22.2,19.89)
TL_AVDD3_S3: length 9.7
  TOP w0.2: C131.1 43.85,13.4 43.2,13.4 42.5,14.1 U19.23 ; R104.2 v1(38.09,19.82) ; C128.1 42.7,17.45 42.7,16.78 42.02,16.1 U19.28
  TOP w0.3: C128.1 43.6,18.8 v1(43.2,19.2) ; v1(45.1,12.3) 45.1,12.5 44.85,12.75 C131.1
TL_PA0_MCLK_OUT: length 51.4
  TOP w0.2: v1(25.6,9.5) 25.6,7.3 26.1,6.8 26.1,1.9 26.8,1.2 36.29,1.2 J16.14 J16.13 ; v1(23.5,34.68) 23.5,34.6 23.35,34.45 U3.54
  BOTTOM w0.2: v1(23.5,34.68) 22.83,34.68 22.3,34.15 22.3,27 26.1,23.2 26.1,10.47 25.6,9.97 v1(25.6,9.5)
TL_PA5_DM_M: length 14.1
  TOP w0.2: U3.55 22.95,34.4 22.75,34.6 13.15,34.6 R45.2
TL_PA6_DP_M: length 13
  TOP w0.2: R65.2 12.9,33.85 U3.56
TL_PA7_SWS_M: length 36
  TOP w0.2: U3.1 15.6,33 13.5,30.9 13.5,20.73 12.9,20.13 v1(12.9,19.5) ; J97.5 14.67,6.03 14.4,6.3 v1(14.4,11.6)
  BOTTOM w0.2: v1(14.4,11.6) 14.4,18 v1(12.9,19.5)
TL_PB2_UTX: length 45.7
  TOP w0.2: U3.4 16.12,31.8 14.7,30.38 14.7,19.5 16.6,17.6 16.6,7.5 19,5.1 19,4.2 18.5,3.7 10.87,3.7 J97.2
TL_PB3_URX: length 45.5
  TOP w0.2: J97.4 13.55,1 18.6,1 19.4,1.8 19.4,5.3 17,7.7 17,17.8 15.1,19.7 15.1,30.25 16.25,31.4 U3.5
TL_PC4_ADC_LR: length 29.2
  TOP w0.2: U3.24 26.15,25.67 v1(26.6,25.22) ; v1(26.9,9.5) v1(26.9,7)
  BOTTOM w0.2: v1(26.9,9.5) 26.9,24.1 26.6,24.4 v1(26.6,25.22) ; J16.11 33.07,7 v1(26.9,7)
TL_PC5_ADC_DAT: length 23.4
  TOP w0.2: v1(27.4,25.2) 26.55,26.05 U3.25 ; J16.7 27.6,7.39 v1(27.6,9.5)
  BOTTOM w0.2: v1(27.6,9.5) 27.6,9.97 27.27,10.3 27.27,23.97 27.4,24.1 v1(27.4,25.2)
TL_PD1_LED2_M: length 14.7
  TOP w0.2: U3.37 30.18,31 31.98,32.8 37.1,32.8 40.08,29.82 R3.1
TL_PD2_LED1_M: length 13
  TOP w0.2: R2.1 39.25,31.25 37.3,33.2 31.85,33.2 30.05,31.4 U3.38
TL_PD3_24M_CLK_OUT: length 5
  TOP w0.2: R23.1 32.01,33.9 29.91,31.8 U3.39
TL_PD4_BUTTON1_M: length 22.8
  TOP w0.2: SW4.1 48.35,37.88 45.47,35 32.58,35 29.78,32.2 U3.40
TL_PD5_BUTTON2_M: length 18.2
  TOP w0.2: SW3.1 43.65,37.55 41.5,35.4 32.46,35.4 29.66,32.6 U3.41
TL_PD6_BUTTON3_M: length 13.6
  TOP w0.2: U3.42 29.54,33 32.34,35.8 37.56,35.8 39.15,37.39 SW2.1
TL_PE0_I2C_SCK_M: length 18.8
  TOP w0.2: J3.1 13.82,41.21 13.86,41.17 R14.2 13.86,36.65 14.3,36.2 19.5,36.2 19.76,35.94 24.17,35.94 25.35,34.76 U3.49
TL_PE2_I2C_SDA_M: length 19.9
  TOP w0.2: U3.50 24.95,34.64 24.02,35.57 19.53,35.57 19.3,35.8 13.8,35.8 12.85,36.76 R13.2 12.85,40.72 J3.2
TL_PE3_LED1_M: length 16.7
  TOP w0.2: U3.51 v1(24.55,33.08) ; R119.1 v1(39,33.95)
  BOTTOM w0.2: v1(39,33.95) 38.13,33.08 v1(24.55,33.08)
TL_PE3_LED_S1: length 2.3
  TOP w0.2: U5.38 3.95,17.29 3.19,18.05 R109.1
TL_PE3_LED_S2: length 2.5
  TOP w0.2: U6.38 21.15,17.17 20.92,17.4 20.5,17.4 20.12,17.78 R110.1
TL_PE3_LED_S3: length 2.5
  TOP w0.2: U19.38 37.05,17.27 36.48,17.84 36.03,17.84 R111.1
TL_RFVDD1V4_M: length 17
  TOP w0.15: 26.23,35.52 26.45,35.3 26.45,34.54 26.55,34.45 U3.46
  TOP w0.2: U3.32 31.4,29
  TOP w0.3: C22.1 v1(35.9,27) v1(35.9,26.5) ; C22.1 35.9,28.5 C20.1 35.2,29.2 31.6,29.2 31.4,29 ; C22.1 35.03,27.5 L5.2 ; v1(23,37.2) C9.1 C10.1 26.23,35.52
TL_RFVDD1V4_S1: length 13.4
  TOP w0.2: v1(8.3,18.1) C29.1 C30.1 6.6,17.63 6.35,17.38 U5.32 ; U5.25 9.5,14.8 10.1,15.4 13.43,15.4 13.83,15 C37.1
  TOP w0.3: L7.2 13.75,14.45 C40.1 ; v1(13.8,13.3) 14.3,13.8 C40.1 ; C40.1 C37.1
TL_RFVDD1V4_S2: length 13.7
  TOP w0.2: U6.32 23.55,17.17 23.7,17.32 C45.1 C44.1 v1(25.32,18.1) ; U6.25 26.87,14.8 27.47,15.4 31.1,15.4 C55.1
  TOP w0.3: v1(31,12.9) 31.5,13.4 C52.1 ; C52.1 30.95,14.45 L9.2 ; C52.1 C55.1
TL_RFVDD1V4_S3: length 13.6
  TOP w0.2: U19.25 42.7,14.9 43.22,15.42 47.08,15.42 C127.1 ; U19.32 39.45,17.45 39.7,17.7 C136.1 C135.1 v1(41.38,18.2)
  TOP w0.3: C133.1 47.4,13.3 v1(47.1,13) ; C133.1 46.85,14.55 L10.2 ; C133.1 C127.1
TL_RST_M: length 9.4
  TOP w0.2: U3.43 29.12,33.85 30.45,35.18 C11.1 30.45,36.12 32.93,38.6 SW1.1
TL_VBAT: length 38.5
  TOP w0.2: U19.22 42.1,13.7 43.05,12.75 C130.1 ; U5.22 8.97,13.6 9.45,13.12 v1(9.45,12.65) C39.1 ; U3.29 29.9,27.8 30.1,27.6 ; 27.33,12.65 26.38,13.6 U6.22
  TOP w0.3: 30.1,27.6 30.1,26.3 31.4,25 C21.1 v1(32.2,24.3) ; v1(42.4,12.2) 42.85,12.2 C130.1 ; C54.1 26.57,12.65 26.02,12.1 v1(25.5,12.1)
  TOP w0.5: 11.9,24 12.3,24 v1(12.6,23.7) ; 11.9,24 R68.2 11.2,24.7 C122.1 9.63,25.5 9.18,25.05 U18.2 1.35,25.05 ; 11.9,24 v1(12.5,24.6)
  BOTTOM w0.5: v1(16,10) v1(15.5,9.5) 13.02,11.98 10.12,11.98 v1(9.45,12.65)
TL_XC1_M: length 12.4
  TOP w0.2: U3.47 26.15,34.33 26.1,34.38 26.1,35.05 24.48,36.68 21.05,36.68 C12.2 19.4,38.33 19.4,39.68 20.59,40.87 Y1.3
TL_XC2_M: length 10.8
  TOP w0.2: U3.48 25.72,33.88 25.72,34.91 24.32,36.31 19.91,36.31 C13.2 18.11,38.12 18.11,38.94
TL_XC2_S1: length 2.7
  TOP w0.2: R33.1 R32.1 5.29,17.61 5.55,17.35 U5.34
TL_XC2_S2: length 2.8
  TOP w0.2: R42.1 R41.1 22.75,17.55 U6.34
TL_XC2_S3: length 2.8
  TOP w0.2: U19.34 38.65,17.64 R104.1 R105.1
N20339251: length 3
  TOP w0.2: C18.1 U3.13
N20339567: length 2.9
  TOP w0.2: U3.15 22.55,25.87 22.5,25.82 22.48,25.82 22.18,25.52 22.18,25.5 21.6,24.92 C23.1
N20339740: length 3
  TOP w0.2: U3.23 25.75,25.25 26.55,24.45 26.56,24.45 C26.1
N20340124: length 4.3
  TOP w0.2: U3.34 30.64,29.8 30.86,30.02
  TOP w0.3: L4.1 31.49,30.65 30.86,30.02
N20340134: length 4.2
  TOP w0.2: U3.31 29.22,28.6 29.24,28.58 31.12,28.58
  TOP w0.3: L5.1 31.7,28 31.12,28.58
N20349172: length 2.4
  TOP w0.2: C38.1 U5.8
N20349354: length 2
  TOP w0.2: U5.9 3.15,11.75 3.55,11.35 C41.1
N20350037: length 1.9
  TOP w0.2: C43.1 6.15,11.83 5.95,12.03 U5.16
N20350580: length 2.5
  TOP w0.2: 9.85,14.45 9.8,14.4 U5.24
  TOP w0.3: 9.85,14.45 L7.1
N20350582: length 3.2
  TOP w0.2: 9.7,16.2 9.1,15.6 U5.27
  TOP w0.3: L6.1 10.11,16.85 9.7,16.44 9.7,16.2
N20367658: length 2.4
  TOP w0.2: C53.1 U6.8
N20367674: length 2
  TOP w0.2: C56.1 20.75,11.32 20.35,11.72 U6.9
N20367749: length 1.9
  TOP w0.2: C58.1 23.45,11.32 23.15,11.62 U6.16
N20367829: length 2.5
  TOP w0.2: 27.23,14.4 U6.24
  TOP w0.3: L9.1 27.28,14.45 27.23,14.4
N20367831: length 3.1
  TOP w0.2: U6.27 26.58,15.6 27.83,16.85 L8.1
N20435584: length 4.1
  TOP w0.5: L3.2 C6.2 J88.1
N20442183: length 3.1
  TOP w0.2: U3.8 19.7,30.2 19.55,30.05 C59.2
N20442186: length 3.3
  TOP w0.2: C60.2 19.32,29.12 20,29.8 U3.9
N20446937: length 2
  TOP w0.2: J30.3 9.25,36.5 R65.1
N20446945: length 1.9
  TOP w0.2: J30.2 8.98,37.3 9.08,37.2 R45.1
N20447032: length 1
  TOP w0.5: R101.1 R69.2
N20447038: length 3.5
  TOP w0.5: U18.1 8.71,22.75 8.81,22.85 R69.1 R68.1
N20447058: length 1
  TOP w0.5: R102.1 R101.2
N20449953: length 2.4
  TOP w0.2: C123.1 U19.8
N20449969: length 1.9
  TOP w0.2: C125.1 36.45,11.42 36.25,11.62 U19.9
N20450013: length 1.8
  TOP w0.2: U19.16 C126.1
N20450064: length 3.1
  TOP w0.2: L11.1 43.55,16.95 42.3,15.7 U19.27
N20450066: length 2.5
  TOP w0.2: L10.1 43.18,14.55 43.13,14.5 U19.24
N20490300: length 1.5
  TOP w0.2: R109.2 1.24,18.53 D4.A
N20490451: length 1.7
  TOP w0.2: R110.2 19.12,18.82 D5.A
N20490658: length 1.9
  TOP w0.2: R111.2 34.15,18.25 33.69,18.71 D6.A
N20496511: length 6.7
  TOP w0.2: R1.2 19.11,35.15 19.16,35.2 23.8,35.2 24.15,34.85 U3.52
N20499472: length 1.6
  TOP w0.2: U5.4 1.8,14.8 1.38,14.38 C141.2
N20499474: length 1.6
  TOP w0.2: C140.2 1.42,15.52 1.74,15.2 U5.3
N20499818: length 1.6
  TOP w0.2: U6.4 18.62,14.8 C142.2
N20499820: length 1.5
  TOP w0.2: C143.2 18.67,15.43 18.89,15.2 U6.3
N20500173: length 1.7
  TOP w0.2: U19.4 34.73,14.9 C144.2
N20500175: length 1.4
  TOP w0.2: U19.3 34.59,15.3 34.57,15.32 C145.2
N20500676: length 6.6
  TOP w0.2: R112.2 51.38,7.47 53.23,9.33 J4.3
N202186321: length 1.6
  TOP w0.2: R2.2 D1.A
N202186660: length 1.6
  TOP w0.2: R3.2 D2.A
N205071311: length 1.6
  TOP w0.2: R119.2 D7.A

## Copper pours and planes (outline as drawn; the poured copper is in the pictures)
GND on TOP: 2,0.2 0.73,0.73 0.2,2 0.2,42 0.73,43.27 2,43.8 25.4,43.8 25.4,39.6 26.2,39 26.2,34.8 27.7,34.8 27.7,39 28.5,39.6 28.5,43.8 61,43.8 62.27,43.27 62.8,42 62.8,2 62.27,0.73 61,0.2 ; 17 cut-outs
GND on BOTTOM: 2,0.2 0.73,0.73 0.2,2 0.2,42 0.73,43.27 2,43.8 61,43.8 62.27,43.27 62.8,42 62.8,2 62.27,0.73 61,0.2 ; 5 cut-outs
GND on GND: 2,0.2 0.73,0.73 0.2,2 0.2,42 0.73,43.27 2,43.8 61,43.8 62.27,43.27 62.8,42 62.8,2 62.27,0.73 61,0.2 ; 5 cut-outs
VBUS on POWER: 2,0.2 0.73,0.73 0.2,2 0.2,42 0.73,43.27 2,43.8 10.4,43.8 10.4,21.3 4.76,21.3 3.9,20.44 3.9,16.94 3.4,16.44 3.4,9.66 4.26,8.8 10.8,8.8 10.8,0.2
TL_AVD_M on POWER: 22.64,24.7 22.4,24.94 22.4,26.96 26.04,30.6 38.36,30.6 38.7,30.26 38.7,29.64 38.06,29 34.46,29 31.1,25.64 31.1,25.1 25.66,25.1 25.26,24.7 ; 1 cut-out
TL_AVD_S1 on POWER: 4.34,9 3.6,9.74 3.6,16.36 4,16.76 9.16,11.6 14.24,11.6 15.5,12.86 15.5,14.54 11.64,18.4 12.2,18.96 12.2,20.3 14.06,20.3 17.5,16.86 17.5,12.74 13.76,9 ; 2 cut-outs
TL_AVD_S2 on POWER: 28.14,18.4 30.4,20.66 33.7,17.36 33.7,9.7 20.64,9.7 20,10.34 20,12.2 22.66,12.2 23.56,11.3 30.84,11.3 31.5,11.96 31.5,15.04 ; 1 cut-out
TL_AVD_S3 on POWER: 33.9,9.7 33.9,12.5 38.96,12.5 39.76,11.7 46.54,11.7 47.6,12.76 47.6,15.04 44.1,18.54 44.1,18.96 46.24,21.1 46.26,21.1 50.9,16.46 50.9,11.44 49.16,9.7
TL_AVDD3_M on POWER: 31.3,25.1 31.3,25.56 34.54,28.8 38.14,28.8 38.9,29.56 38.9,30.34 38.44,30.8 17.64,30.8 10.6,37.84 10.6,39.9 21.36,39.9 23.16,38.1 21.9,36.84 21.9,35.56 22.46,35 39.46,35 41.1,33.36 41.1,28.24 40.66,27.8 35.36,27.8 34.9,27.34 34.9,25.1
TL_AVDD3_S1 on POWER: 9.24,11.8 4.1,16.94 4.1,20.36 4.84,21.1 11.26,21.1 12,20.36 12,19.04 11.46,18.5 10.24,18.5 9.64,19.1 6.96,19.1 6.5,18.64 6.5,18.36 7.86,17 9.16,17 13.6,12.56 13.6,11.8
TL_AVDD3_S2 on POWER: 27.1,11.5 27.1,12.24 24.14,15.2 20,15.2 20,20.8 30.26,20.8 27.96,18.5 26.34,18.5 25.84,19 22.96,19 22.26,18.3 23.46,17.1 24.76,17.1 29.4,12.46 29.4,11.84 29.06,11.5
TL_AVDD3_S3 on POWER: 43.6,11.9 43.6,12.34 42.34,13.6 41.04,13.6 37.4,17.24 37.4,21.7 45.66,21.7 46.11,21.25 43.9,19.04 43.9,18.6 42.04,18.6 41.44,19.2 40.2,19.2 40.2,17.66 45.6,12.26 45.6,11.9
TL_RFVDD1V4_M on POWER: 35.1,25.1 35.1,27.26 35.44,27.6 40.74,27.6 41.3,28.16 41.3,33.44 39.54,35.2 22.54,35.2 22.1,35.64 22.1,36.76 23.34,38 41.06,38 44.7,34.36 44.7,27.94 42.16,25.4 36.26,25.4 35.96,25.1
TL_RFVDD1V4_S1 on POWER: 13.8,11.8 13.8,12.64 9.24,17.2 7.94,17.2 6.7,18.44 6.7,18.56 7.04,18.9 9.56,18.9 10.16,18.3 11.46,18.3 15.3,14.46 15.3,12.94 14.16,11.8
TL_RFVDD1V4_S2 on POWER: 29.34,11.5 29.6,11.76 29.6,12.54 24.84,17.3 23.54,17.3 22.54,18.3 23.04,18.8 25.76,18.8 26.26,18.3 27.96,18.3 31.3,14.96 31.3,12.04 30.76,11.5
TL_RFVDD1V4_S3 on POWER: 45.8,11.9 45.8,12.34 40.4,17.74 40.4,19 41.36,19 41.96,18.4 43.96,18.4 47.4,14.96 47.4,12.84 46.46,11.9
TL_VBAT on POWER: 11,0.2 11,8.8 13.84,8.8 17.7,12.66 17.7,16.94 14.14,20.5 12.14,20.5 11.34,21.3 10.6,21.3 10.6,37.56 17.56,30.6 25.76,30.6 22.2,27.04 22.2,24.86 22.56,24.5 25.34,24.5 25.74,24.9 36.04,24.9 36.34,25.2 42.24,25.2 44.9,27.86 44.9,34.44 41.14,38.2 23.34,38.2 21.44,40.1 10.6,40.1 10.6,43.8 61,43.8 62.27,43.27 62.8,42 62.8,2 62.27,0.73 61,0.2 ; 11 cut-outs

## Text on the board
Ref Des/Silkscreen Bottom: TLSR9517CBAR56D | 2021-09-09 | C1T253A91_V1_1_20210909 | VBUS | PB2 | PB3 | VBAT | SWS | GND | DAT_S3 | DAT_S2 | DAT_S1 | DAT | DAT_M | BITCLK | LRCLK | MCLK | I2S_IN | I2S_OUT
User.Comments: CR_UNNAMED_2 | CR_UNNAMED_3
Ref Des/Silkscreen Top: SDA | SCK | I2C | I2S | MIC_IN | SPK_R | SPK_L | RST
NCLEGEND-1-4: FIGURE | SIZE | 0.3 | 0.9 | 1.0 | DRILL CHART: TOP to BOTTOM | ALL UNITS ARE IN MILLIMETERS | PLATED | NON-PLATED | QTY | 294 | 26 | 6 | 2
